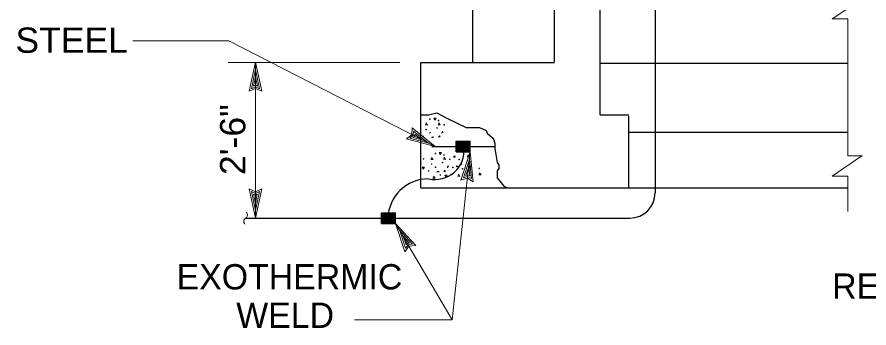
# Model space of a CAD drawing. Extents: x -39.6 to 16.1, y -17.6 to 34.
# Drawn here: x -9.263 to -5.055, y 5.263 to 6.798 of the extents above; entities that cross this region are included whole.
import ezdxf
from ezdxf.enums import TextEntityAlignment as Align

# ---------------------------------------------------------------- set-up
doc = ezdxf.new("R2010")
doc.units = 0
doc.header["$LTSCALE"] = 0.05
doc.layers.add('1', color=7, linetype='Continuous', lineweight=13)
doc.layers.add('2', color=7, linetype='Continuous', lineweight=13)

msp = doc.modelspace()

# ---------------------------------------------------------------- linework, layer by layer
at = {"layer": '1', "lineweight": 25}
for p, q in [((-7.01121, 6.57442), (-7.01121, 7.12442)), ((-6.60821, 6.57642), (-6.60821, 7.12442)), ((-6.38321, 6.31542), (-6.38321, 7.12442)), ((-6.11121, 7.12442), (-6.11121, 5.93042)), ((-7.26921, 5.95542), (-7.26921, 6.57442)), ((-7.26921, 6.57442), (-6.60821, 6.57442)), ((-6.38321, 6.57042), (-5.15921, 6.57042)), ((-6.38321, 6.31542), (-6.24121, 6.31542)), ((-6.24121, 5.95542), (-6.24121, 6.30942)), ((-6.24121, 6.22942), (-5.15921, 6.22942)), ((-7.09321, 6.13242), (-7.09321, 6.18542)), ((-7.09321, 6.18542), (-7.02421, 6.18542)), ((-7.02421, 6.13242), (-7.02421, 6.18542)), ((-7.21421, 6.15842), (-6.90421, 6.15842)), ((-7.09321, 6.18442), (-7.02421, 6.18442)), ((-7.09321, 6.18342), (-7.02421, 6.18342)), ((-7.09321, 6.18242), (-7.02421, 6.18242)), ((-7.09321, 6.18142), (-7.02421, 6.18142)), ((-7.09321, 6.18042), (-7.02421, 6.18042)), ((-7.09321, 6.17942), (-7.02421, 6.17942)), ((-7.09321, 6.17842), (-7.02421, 6.17842)), ((-7.09321, 6.17742), (-7.02421, 6.17742)), ((-7.09321, 6.17642), (-7.02421, 6.17642)), ((-7.09321, 6.17542), (-7.02421, 6.17542)), ((-7.09321, 6.17442), (-7.02421, 6.17442)), ((-7.09321, 6.17342), (-7.02421, 6.17342)), ((-7.09321, 6.17242), (-7.02421, 6.17242)), ((-7.09321, 6.17142), (-7.02421, 6.17142)), ((-7.09321, 6.17042), (-7.02421, 6.17042)), ((-7.09321, 6.16942), (-7.02421, 6.16942)), ((-7.09321, 6.16842), (-7.02421, 6.16842)), ((-7.09321, 6.16742), (-7.02421, 6.16742)), ((-7.09321, 6.16642), (-7.02421, 6.16642)), ((-7.09321, 6.16542), (-7.02421, 6.16542)), ((-7.09321, 6.16442), (-7.02421, 6.16442)), ((-7.09321, 6.16342), (-7.02421, 6.16342)), ((-7.09321, 6.16242), (-7.02421, 6.16242)), ((-7.09321, 6.16142), (-7.02421, 6.16142)), ((-7.09321, 6.16042), (-7.02421, 6.16042)), ((-7.09321, 6.15942), (-7.02421, 6.15942)), ((-7.09321, 6.15842), (-7.02421, 6.15842)), ((-7.09321, 6.15742), (-7.02421, 6.15742)), ((-7.09321, 6.15642), (-7.02421, 6.15642)), ((-7.09321, 6.15542), (-7.02421, 6.15542)), ((-7.09321, 6.15442), (-7.02421, 6.15442)), ((-7.09321, 6.15342), (-7.02421, 6.15342)), ((-7.09321, 6.15242), (-7.02421, 6.15242)), ((-7.09321, 6.15142), (-7.02421, 6.15142)), ((-7.09321, 6.15042), (-7.02421, 6.15042)), ((-7.09321, 6.14942), (-7.02421, 6.14942)), ((-7.09321, 6.14842), (-7.02421, 6.14842)), ((-7.09321, 6.14742), (-7.02421, 6.14742)), ((-7.09321, 6.14642), (-7.02421, 6.14642)), ((-7.09321, 6.14542), (-7.02421, 6.14542)), ((-7.09321, 6.14442), (-7.02421, 6.14442)), ((-7.09321, 6.14342), (-7.02421, 6.14342)), ((-7.09321, 6.14242), (-7.02421, 6.14242)), ((-7.09321, 6.14142), (-7.02421, 6.14142)), ((-7.09321, 6.14042), (-7.02421, 6.14042)), ((-7.09321, 6.13942), (-7.02421, 6.13942)), ((-7.09321, 6.13842), (-7.02421, 6.13842)), ((-7.09321, 6.13742), (-7.02421, 6.13742)), ((-7.09321, 6.13642), (-7.02421, 6.13642)), ((-7.09321, 6.13542), (-7.02421, 6.13542)), ((-7.09321, 6.13442), (-7.02421, 6.13442)), ((-7.09321, 6.13342), (-7.02421, 6.13342)), ((-7.09321, 6.13242), (-7.02421, 6.13242)), ((-7.26921, 5.95542), (-5.15921, 5.95542)), ((-7.46221, 5.77942), (-7.46221, 5.83242)), ((-7.46221, 5.83242), (-7.39321, 5.83242)), ((-7.46221, 5.83142), (-7.39321, 5.83142)), ((-7.46221, 5.83042), (-7.39321, 5.83042)), ((-7.46221, 5.82942), (-7.39321, 5.82942)), ((-7.46221, 5.82842), (-7.39321, 5.82842)), ((-7.46221, 5.82742), (-7.39321, 5.82742)), ((-7.46221, 5.82642), (-7.39321, 5.82642)), ((-7.46221, 5.82542), (-7.39321, 5.82542)), ((-7.46221, 5.82442), (-7.39321, 5.82442)), ((-7.46221, 5.82342), (-7.39321, 5.82342)), ((-7.46221, 5.82242), (-7.39321, 5.82242)), ((-7.46221, 5.82142), (-7.39321, 5.82142)), ((-7.46221, 5.82042), (-7.39321, 5.82042)), ((-7.46221, 5.81942), (-7.39321, 5.81942)), ((-7.46221, 5.81842), (-7.39321, 5.81842)), ((-7.46221, 5.81742), (-7.39321, 5.81742)), ((-7.46221, 5.81642), (-7.39321, 5.81642)), ((-7.46221, 5.81542), (-7.39321, 5.81542)), ((-7.46221, 5.81442), (-7.39321, 5.81442)), ((-7.46221, 5.81342), (-7.39321, 5.81342)), ((-7.46221, 5.81242), (-7.39321, 5.81242)), ((-7.46221, 5.81142), (-7.39321, 5.81142)), ((-7.46221, 5.81042), (-7.39321, 5.81042)), ((-7.46221, 5.80942), (-7.39321, 5.80942)), ((-7.46221, 5.80842), (-7.39321, 5.80842)), ((-7.46221, 5.80742), (-7.39321, 5.80742)), ((-7.46221, 5.80642), (-7.39321, 5.80642)), ((-7.39321, 5.77942), (-7.39321, 5.83242)), ((-8.13521, 5.80542), (-6.23621, 5.80542)), ((-7.46221, 5.80542), (-7.39321, 5.80542)), ((-7.46221, 5.80442), (-7.39321, 5.80442)), ((-7.46221, 5.80342), (-7.39321, 5.80342)), ((-7.46221, 5.80242), (-7.39321, 5.80242)), ((-7.46221, 5.80142), (-7.39321, 5.80142)), ((-7.46221, 5.80042), (-7.39321, 5.80042)), ((-7.46221, 5.79942), (-7.39321, 5.79942)), ((-7.46221, 5.79842), (-7.39321, 5.79842)), ((-7.46221, 5.79742), (-7.39321, 5.79742)), ((-7.46221, 5.79642), (-7.39321, 5.79642)), ((-7.46221, 5.79542), (-7.39321, 5.79542)), ((-7.46221, 5.79442), (-7.39321, 5.79442)), ((-7.46221, 5.79342), (-7.39321, 5.79342)), ((-7.46221, 5.79242), (-7.39321, 5.79242)), ((-7.46221, 5.79142), (-7.39321, 5.79142)), ((-7.46221, 5.79042), (-7.39321, 5.79042)), ((-7.46221, 5.78942), (-7.39321, 5.78942)), ((-7.46221, 5.78842), (-7.39321, 5.78842)), ((-7.46221, 5.78742), (-7.39321, 5.78742)), ((-7.46221, 5.78642), (-7.39321, 5.78642)), ((-7.46221, 5.78542), (-7.39321, 5.78542)), ((-7.46221, 5.78442), (-7.39321, 5.78442)), ((-7.46221, 5.78342), (-7.39321, 5.78342)), ((-7.46221, 5.78242), (-7.39321, 5.78242)), ((-7.46221, 5.78142), (-7.39321, 5.78142)), ((-7.46221, 5.78042), (-7.39321, 5.78042)), ((-7.46221, 5.77942), (-7.39321, 5.77942))]:
    msp.add_line(p, q, dxfattribs=at)
at = {"layer": '1'}
for p, q in [((-5.23621, 6.78842), (-5.09121, 6.88842)), ((-5.23621, 6.78842), (-5.15921, 6.78842)), ((-5.15921, 6.11242), (-5.15921, 6.78842)), ((-7.37221, 6.57442), (-8.21921, 6.57442)), ((-8.08521, 6.57542), (-8.11621, 6.43142)), ((-8.08521, 5.80542), (-8.08521, 6.57542)), ((-8.08521, 6.57542), (-8.05421, 6.43142)), ((-8.08521, 6.53842), (-8.10521, 6.44442)), ((-8.08521, 6.53842), (-8.06521, 6.44442)), ((-8.08521, 6.50242), (-8.09421, 6.45742)), ((-8.08521, 6.50242), (-8.07521, 6.45742)), ((-8.08521, 6.45342), (-8.10521, 6.44442)), ((-8.08521, 6.46142), (-8.09421, 6.45742)), ((-8.07521, 6.45742), (-8.08521, 6.46142)), ((-8.06521, 6.44442), (-8.08521, 6.45342)), ((-7.19721, 6.15842), (-7.31121, 6.25142)), ((-7.30621, 6.21442), (-7.30521, 6.23542)), ((-7.23021, 6.17542), (-7.30521, 6.23542)), ((-7.32321, 6.20042), (-7.30621, 6.21442)), ((-7.23021, 6.17542), (-7.32321, 6.20042)), ((-7.30721, 6.20342), (-7.29821, 6.21042)), ((-7.26221, 6.19142), (-7.30721, 6.20342)), ((-7.26221, 6.19142), (-7.29821, 6.22042)), ((-7.29821, 6.21042), (-7.29821, 6.22042)), ((-7.11421, 5.30342), (-7.02421, 6.13242)), ((-7.02421, 6.13242), (-7.07021, 5.99242)), ((-7.02421, 6.13242), (-7.00921, 5.98542)), ((-5.23621, 6.01242), (-5.09121, 6.11242)), ((-5.15921, 6.11242), (-5.08721, 6.11242)), ((-7.02821, 6.09542), (-7.05821, 6.00442)), ((-7.03221, 6.05942), (-7.04621, 6.01642)), ((-7.03221, 6.05942), (-7.02721, 6.01442)), ((-7.02821, 6.09542), (-7.01821, 6.00042)), ((-7.03621, 6.01942), (-7.04621, 6.01642)), ((-7.02721, 6.01442), (-7.03621, 6.01942)), ((-7.03721, 6.01142), (-7.05821, 6.00442)), ((-7.01821, 6.00042), (-7.03721, 6.01142)), ((-5.23621, 6.01242), (-5.15921, 6.01242)), ((-5.15921, 5.83842), (-5.15921, 6.01242)), ((-8.08521, 5.80542), (-8.11621, 5.94942)), ((-8.08521, 5.84242), (-8.10521, 5.93642)), ((-8.10521, 5.93642), (-8.08521, 5.92742)), ((-8.08521, 5.80542), (-8.05421, 5.94942)), ((-8.08521, 5.84242), (-8.06521, 5.93642)), ((-8.08521, 5.92742), (-8.06521, 5.93642)), ((-8.08521, 5.87842), (-8.09521, 5.92342)), ((-8.09521, 5.92342), (-8.08521, 5.91942)), ((-8.08521, 5.87842), (-8.07621, 5.92342)), ((-8.08521, 5.91942), (-8.07621, 5.92342)), ((-7.11421, 5.30342), (-7.39321, 5.77942)), ((-7.39321, 5.77942), (-7.29321, 5.67042)), ((-7.39321, 5.77942), (-7.34721, 5.63942)), ((-7.37421, 5.74742), (-7.31021, 5.67642)), ((-7.37421, 5.74742), (-7.34421, 5.65642)), ((-7.35621, 5.71642), (-7.34121, 5.67342)), ((-7.35621, 5.71642), (-7.32521, 5.68242)), ((-7.33521, 5.68142), (-7.34121, 5.67342)), ((-7.32521, 5.68242), (-7.33521, 5.68142)), ((-7.33121, 5.67442), (-7.34421, 5.65642)), ((-7.31021, 5.67642), (-7.33121, 5.67442)), ((-7.59621, 5.30342), (-7.11421, 5.30342))]:
    msp.add_line(p, q, dxfattribs=at)
for points in [[(-8.69021, 6.68042), (-8.21721, 6.68042), (-7.19721, 6.15842), (-7.33921, 6.19642)], [(-8.05421, 6.43142), (-8.08521, 6.44542), (-8.11621, 6.43142)], [(-7.33921, 6.19642), (-7.31321, 6.21742), (-7.31121, 6.25142)], [(-7.00921, 5.98542), (-7.03821, 6.00342), (-7.07021, 5.99242)], [(-8.11621, 5.94942), (-8.08521, 5.93542), (-8.05421, 5.94942)], [(-7.29321, 5.67042), (-7.32721, 5.66742), (-7.34721, 5.63942)]]:
    msp.add_lwpolyline(points, dxfattribs=at)
at = {"layer": '1', "lineweight": 25}
msp.add_lwpolyline([(-7.26921, 6.31542), (-7.23121, 6.31542), (-7.18921, 6.32442), (-7.14021, 6.29942), (-7.04421, 6.25342), (-7.02821, 6.25342), (-6.97821, 6.25342), (-6.94521, 6.23742), (-6.94121, 6.22442), (-6.91621, 6.20342), (-6.90721, 6.19142), (-6.90321, 6.17442), (-6.90321, 6.14942), (-6.89521, 6.10042), (-6.89121, 6.07942), (-6.88321, 6.06742), (-6.88321, 6.05042), (-6.89121, 6.03842), (-6.89121, 6.00442), (-6.87821, 5.98842), (-6.85821, 5.96342), (-6.84121, 5.95542)], dxfattribs=at)
for centre, radius, start, end in [((-7.19826, 6.13963), 0.14381, 257.16263, 5.90091), ((-7.23047, 5.7985), 0.20086, 89.92472, 178.02778), ((-6.23621, 5.93042), 0.125, 270, 0)]:
    msp.add_arc(centre, radius, start, end, dxfattribs=at)
at = {"layer": '1'}
for centre, start, end in [((-8.14308, 5.82067), 302.92471, 49.18492), ((-8.12533, 5.79017), 122.92471, 229.18492)]:
    msp.add_arc(centre, 0.01817, start, end, dxfattribs=at)
at = {"layer": '2'}
msp.add_line((-7.10721, 6.10842), (-7.10021, 6.11342), dxfattribs=at)
for points in [[(-7.24121, 6.27542), (-7.24621, 6.26542), (-7.23521, 6.26442), (-7.24321, 6.27542)], [(-7.19921, 6.29042), (-7.20421, 6.29942), (-7.19321, 6.29942), (-7.19921, 6.28842)], [(-7.17821, 6.27642), (-7.18321, 6.26642), (-7.17321, 6.26542), (-7.18121, 6.27642)], [(-7.21421, 6.20442), (-7.20921, 6.20742), (-7.20421, 6.20442), (-7.21621, 6.20242)], [(-7.21421, 6.10542), (-7.21921, 6.09542), (-7.20821, 6.09442), (-7.21621, 6.10542)], [(-7.17221, 6.12042), (-7.17721, 6.12942), (-7.16621, 6.12942), (-7.17221, 6.11842)], [(-7.15121, 6.10642), (-7.15621, 6.09642), (-7.14621, 6.09542), (-7.15421, 6.10642)], [(-7.10021, 6.11342), (-7.09921, 6.10642), (-7.10721, 6.10642)], [(-7.03421, 6.11842), (-7.03921, 6.10842), (-7.02821, 6.10742), (-7.03621, 6.11842)], [(-7.09421, 6.06042), (-7.09021, 6.06442), (-7.08621, 6.06042), (-7.09321, 6.05942)], [(-7.07321, 6.07342), (-7.06821, 6.07542), (-7.06621, 6.07042), (-7.07321, 6.07242)], [(-7.02521, 6.05342), (-7.03021, 6.06142), (-7.01921, 6.06142), (-7.02521, 6.05142)], [(-7.25621, 6.04942), (-7.26121, 6.05742), (-7.25021, 6.05742), (-7.25621, 6.04742)], [(-7.18721, 6.03442), (-7.18221, 6.03742), (-7.17721, 6.03442), (-7.18921, 6.03242)], [(-7.14521, 6.00842), (-7.15021, 6.01742), (-7.13921, 6.01742), (-7.14521, 6.00742)], [(-7.08021, 6.02242), (-7.08521, 6.01242), (-7.07521, 6.01142), (-7.08221, 6.02242)], [(-6.97621, 6.02942), (-6.98121, 6.01942), (-6.97121, 6.01842), (-6.97921, 6.02942)], [(-7.20421, 6.01342), (-7.20921, 6.00342), (-7.19821, 6.00242), (-7.20621, 6.01342)]]:
    msp.add_lwpolyline(points, dxfattribs=at)
for points in [[(-7.16621, 6.22542), (-7.16121, 6.23442), (-7.15821, 6.22842)], [(-7.18121, 6.20442), (-7.17621, 6.21242), (-7.17321, 6.20642)], [(-7.13921, 6.05542), (-7.13421, 6.06442), (-7.13121, 6.05842)], [(-7.15421, 6.03442), (-7.14921, 6.04242), (-7.14621, 6.03642)]]:
    msp.add_lwpolyline(points, close=True, dxfattribs=at)
for centre in [(-7.22346, 6.29429), (-7.18071, 6.28754), (-7.24196, 6.24229), (-7.22271, 6.22704), (-7.18821, 6.25054), (-7.15296, 6.26579), (-7.25721, 6.20854), (-7.19646, 6.12429), (-7.15371, 6.11754), (-7.25471, 6.09754), (-7.21496, 6.07229), (-7.16121, 6.08054), (-7.12596, 6.09579), (-7.07971, 6.09479), (-7.03846, 6.08904), (-7.23021, 6.03854), (-7.19571, 6.05704), (-7.17221, 6.01829), (-7.11821, 6.02079), (-7.11071, 6.05529), (-7.06271, 6.04954), (-7.03746, 6.03179), (-6.98021, 6.05129)]:
    msp.add_circle(centre, 0.00162, dxfattribs=at)

# ---------------------------------------------------------------- texts
at = {"layer": '1', "width": 1.05}
msp.add_text('STEEL', height=0.125, dxfattribs=at).set_placement((-8.99271, 6.62142), align=Align.CENTER)
msp.add_text('2\'-6"', height=0.125, rotation=90, dxfattribs=at).set_placement((-8.13521, 6.19292), align=Align.CENTER)
at = {"layer": '1'}
for s, p in [('EXOTHERMIC', (-7.36021, 5.45342)), ('WELD', (-7.69721, 5.26342))]:
    msp.add_text(s, height=0.125, dxfattribs=at).set_placement(p, align=Align.RIGHT)
msp.add_text('REINFORCING', height=0.125, dxfattribs=at).set_placement((-4.65171, 5.40742), align=Align.CENTER)

doc.saveas('drawing.dxf')
